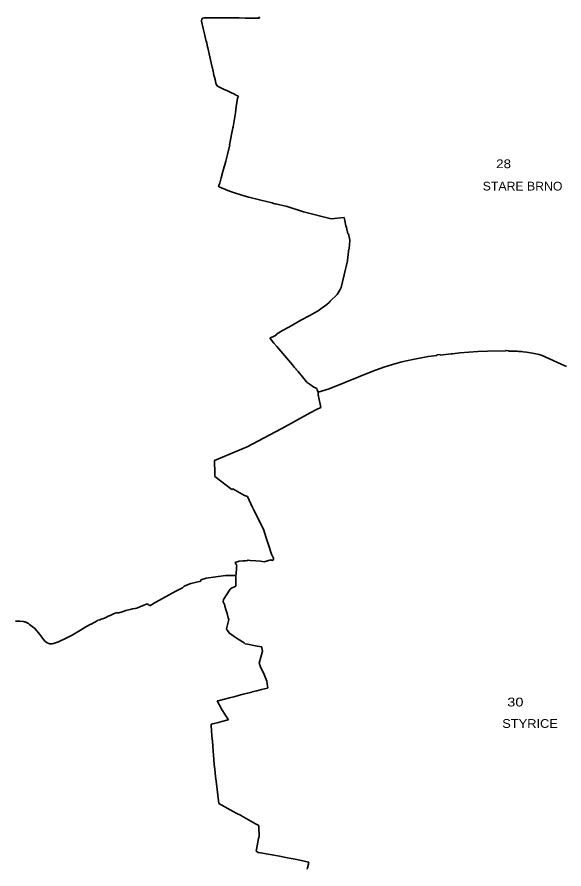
# Model space of a CAD drawing. Extents: x -610940 to -588976, y -1170376 to -1149800.
# Drawn here: x -600639 to -599073, y -1163066 to -1160628 of the extents above; entities that cross this region are included whole.
import ezdxf

# ---------------------------------------------------------------- set-up
doc = ezdxf.new("R2010")
doc.units = 0
doc.header["$LTSCALE"] = 10
doc.layers.add('54', color=7, linetype='Continuous', lineweight=35)
doc.layers.add('55', color=7, linetype='Continuous')
doc.layers.add('56', color=7, linetype='Continuous')

msp = doc.modelspace()

# ---------------------------------------------------------------- linework, layer by layer
at = {"layer": '54'}
for p, q in [((-600103.3, -1160629.78), (-600107.3, -1160631.31)), ((-600103.3, -1160629.78), (-600088.08, -1160629.91)), ((-600085.37, -1160629.93), (-600072.54, -1160630)), ((-600002.59, -1160630.29), (-599986.11, -1160630.73)), ((-599986.11, -1160630.73), (-599979.88, -1160630.93)), ((-599945.32, -1160628.56), (-599945.69, -1160627.27)), ((-599944.67, -1160630.86), (-599945.32, -1160628.56)), ((-600109.32, -1160633.17), (-600110.87, -1160639.41)), ((-600105.68, -1160660.84), (-600110.87, -1160639.41)), ((-600109.32, -1160633.17), (-600107.3, -1160631.31)), ((-599979.88, -1160630.93), (-599979.11, -1160630.96)), ((-599979.11, -1160630.96), (-599965.69, -1160630.92)), ((-600098, -1160693.72), (-600102.01, -1160676.44)), ((-600097.36, -1160696.48), (-600098, -1160693.72)), ((-600095.82, -1160703.17), (-600097.36, -1160696.48)), ((-600093.54, -1160712.95), (-600095.82, -1160703.17)), ((-600092.87, -1160715.78), (-600093.54, -1160712.95)), ((-600080.89, -1160768.02), (-600092.87, -1160715.78)), ((-600080.17, -1160771.14), (-600080.89, -1160768.02)), ((-600079.48, -1160774.16), (-600080.17, -1160771.14)), ((-600077.36, -1160783.38), (-600079.48, -1160774.16)), ((-600076.45, -1160787.46), (-600077.36, -1160783.38)), ((-600076.01, -1160789.45), (-600076.45, -1160787.46)), ((-600069.52, -1160816.92), (-600071.93, -1160807.07)), ((-600069.52, -1160816.92), (-600068.55, -1160820.02)), ((-600066.77, -1160823.08), (-600068.55, -1160820.02)), ((-600066.77, -1160823.08), (-600064.5, -1160825.65)), ((-600061.27, -1160827.81), (-600064.5, -1160825.65)), ((-600058.82, -1160828.98), (-600061.27, -1160827.81)), ((-600036.69, -1160839.42), (-600047.79, -1160834.31)), ((-600015.91, -1160849.13), (-600026.48, -1160844.23)), ((-600017.13, -1160924.54), (-600013.14, -1160901.76)), ((-600020.88, -1160944.64), (-600020.28, -1160942.07)), ((-600020.28, -1160942.07), (-600017.13, -1160924.54)), ((-599699.51, -1161214.79), (-599702.32, -1161201.68)), ((-599685.63, -1161266.21), (-599690, -1161248.08)), ((-599687.71, -1161286.68), (-599687.35, -1161282.76)), ((-599686.26, -1161271.3), (-599685.63, -1161266.21)), ((-599689.73, -1161299.35), (-599689.5, -1161297.25)), ((-599722.11, -1161421.7), (-599714.05, -1161407.67)), ((-599714.05, -1161407.67), (-599710.88, -1161402.16)), ((-599901.13, -1161540.23), (-599914.85, -1161547.36)), ((-599910.52, -1161552.57), (-599914.85, -1161547.36)), ((-599910.52, -1161552.57), (-599903.3, -1161561.19)), ((-599901.13, -1161540.23), (-599895.55, -1161537.33)), ((-599896.4, -1161536.03), (-599895.55, -1161537.33)), ((-599895.23, -1161570.77), (-599903.3, -1161561.19)), ((-599850.32, -1161623.75), (-599895.23, -1161570.77)), ((-599505.29, -1161607.84), (-599461.75, -1161599.91)), ((-599461.75, -1161599.91), (-599436.5, -1161596.37)), ((-599436.65, -1161595.16), (-599427.23, -1161593.95)), ((-599436.5, -1161596.37), (-599436.65, -1161595.16)), ((-599427.23, -1161593.95), (-599426.97, -1161595.51)), ((-599426.97, -1161595.51), (-599396.23, -1161591.99)), ((-599396.23, -1161591.99), (-599392.18, -1161591.53)), ((-599392.18, -1161591.53), (-599370.97, -1161589.44)), ((-599370.97, -1161589.44), (-599319.39, -1161585.61)), ((-599319.39, -1161585.61), (-599292.08, -1161584.67)), ((-599292.08, -1161584.67), (-599240.09, -1161583.7)), ((-599240.09, -1161583.7), (-599240.14, -1161582.76)), ((-599238.59, -1161582.77), (-599232.38, -1161582.84)), ((-599230.74, -1161582.85), (-599230.74, -1161583.8)), ((-599230.74, -1161583.8), (-599218.48, -1161583.93)), ((-599218.48, -1161583.93), (-599218.01, -1161583.89)), ((-599218.01, -1161583.89), (-599214.85, -1161584.1)), ((-599200.08, -1161585.08), (-599203.24, -1161584.87)), ((-599200.08, -1161585.08), (-599199.58, -1161585.1)), ((-599189.94, -1161585.84), (-599179.82, -1161586.62)), ((-599179.82, -1161586.62), (-599163, -1161589.64)), ((-599163, -1161589.64), (-599143.65, -1161594.17)), ((-599143.65, -1161594.17), (-599135.02, -1161596.97)), ((-599135.02, -1161596.97), (-599114.73, -1161605.82)), ((-599114.73, -1161605.82), (-599080.75, -1161621.2)), ((-599850.32, -1161623.75), (-599844.18, -1161630.77)), ((-599606.5, -1161636.65), (-599589.06, -1161630.32)), ((-599589.06, -1161630.32), (-599564, -1161622)), ((-599564, -1161622), (-599537.18, -1161614.79)), ((-599537.18, -1161614.79), (-599505.29, -1161607.84)), ((-599080.75, -1161621.2), (-599065.94, -1161628.12)), ((-599840.06, -1161635.49), (-599844.18, -1161630.77)), ((-599838.52, -1161637.29), (-599840.06, -1161635.49)), ((-599838.52, -1161637.29), (-599837.63, -1161638.37)), ((-599834.1, -1161642.64), (-599837.63, -1161638.37)), ((-599834.1, -1161642.64), (-599821.62, -1161657.7)), ((-599745.4, -1161692.26), (-599615.27, -1161639.75)), ((-599615.27, -1161639.75), (-599606.5, -1161636.65)), ((-599807.8, -1161673.56), (-599799.85, -1161680.09)), ((-599788.86, -1161687.22), (-599799.85, -1161680.09)), ((-599776.36, -1161701.3), (-599757.25, -1161696.22)), ((-599757.25, -1161696.22), (-599745.4, -1161692.26)), ((-599979.51, -1161857.91), (-599882.14, -1161806.57)), ((-600024.12, -1161979.68), (-600072.54, -1161943.35)), ((-600021.31, -1161978.3), (-600024.12, -1161979.68)), ((-599961.47, -1162037.67), (-599962.52, -1162035.22)), ((-599932.79, -1162093.6), (-599961.47, -1162037.67)), ((-599925.25, -1162118.38), (-599932.79, -1162093.6)), ((-599918.57, -1162138.88), (-599925.25, -1162118.38)), ((-599910.5, -1162164.95), (-599918.57, -1162138.88)), ((-599904.71, -1162176.49), (-599910.5, -1162164.95)), ((-599903.75, -1162177.62), (-599904.71, -1162176.49)), ((-600112.4, -1162239.03), (-600097.62, -1162233.99)), ((-600112.4, -1162239.03), (-600112.16, -1162242.62)), ((-600097.62, -1162233.99), (-600042.31, -1162226.63)), ((-600033.31, -1162226.17), (-600012.18, -1162226.15)), ((-600012.46, -1162244.45), (-600012.18, -1162226.15)), ((-600183.82, -1162271.06), (-600164.74, -1162261.15)), ((-600164.74, -1162261.15), (-600160.13, -1162257.05)), ((-600160.13, -1162257.05), (-600158.3, -1162256.28)), ((-600158.3, -1162256.28), (-600141.05, -1162249.04)), ((-600141.05, -1162249.04), (-600112.16, -1162242.62)), ((-600012.76, -1162256.79), (-600012.46, -1162244.45)), ((-600222.07, -1162292.39), (-600202.95, -1162281.63)), ((-600202.95, -1162281.63), (-600183.82, -1162271.06)), ((-600271.06, -1162309.32), (-600265.95, -1162307.55)), ((-600265.95, -1162307.55), (-600264.38, -1162308.65)), ((-600264.38, -1162308.65), (-600260.3, -1162311.49)), ((-600260.3, -1162311.49), (-600258.2, -1162312.95)), ((-600258.2, -1162312.95), (-600240.96, -1162303.07)), ((-600240.96, -1162303.07), (-600222.07, -1162292.39)), ((-600366.85, -1162338.13), (-600364.05, -1162336.83)), ((-600364.05, -1162336.83), (-600352.79, -1162332.42)), ((-600352.79, -1162332.42), (-600350.1, -1162334.51)), ((-600350.1, -1162334.51), (-600335.03, -1162328.94)), ((-600335.03, -1162328.94), (-600327.33, -1162326.6)), ((-600327.33, -1162326.6), (-600314.8, -1162323.43)), ((-600314.8, -1162323.43), (-600308.43, -1162321.7)), ((-600308.43, -1162321.7), (-600301.74, -1162320.9)), ((-600643.07, -1162357.45), (-600634.44, -1162356.94)), ((-600634.44, -1162356.94), (-600630.84, -1162356.73)), ((-600630.84, -1162356.73), (-600620.22, -1162358.38)), ((-600615.57, -1162359.11), (-600611.4, -1162360.5)), ((-600611.4, -1162360.5), (-600606.21, -1162363.37)), ((-600426.32, -1162365.36), (-600409.64, -1162356.23)), ((-600401.4, -1162352.95), (-600398.02, -1162351.71)), ((-600398.02, -1162351.71), (-600388.65, -1162348.25)), ((-600388.65, -1162348.25), (-600383.01, -1162345.61)), ((-600383.01, -1162345.61), (-600375.62, -1162342.2)), ((-600375.62, -1162342.2), (-600374.19, -1162341.56)), ((-600374.19, -1162341.56), (-600372.43, -1162340.72)), ((-600606.21, -1162363.37), (-600602.72, -1162366.32)), ((-600602.72, -1162366.32), (-600595.6, -1162371.79)), ((-600595.6, -1162371.79), (-600588.93, -1162377.45)), ((-600588.93, -1162377.45), (-600582.79, -1162383.92)), ((-600582.79, -1162383.92), (-600576.52, -1162391.45)), ((-600478.14, -1162395.63), (-600462.25, -1162385.44)), ((-600462.25, -1162385.44), (-600445.03, -1162374.73)), ((-600445.03, -1162374.73), (-600443.97, -1162373.94)), ((-600443.97, -1162373.94), (-600427.04, -1162365.7)), ((-600427.04, -1162365.7), (-600426.32, -1162365.36)), ((-600576.52, -1162391.45), (-600567.65, -1162402.59)), ((-600567.65, -1162402.59), (-600559.89, -1162413.15)), ((-600520.42, -1162415.85), (-600496.63, -1162404.65)), ((-600496.63, -1162404.65), (-600478.96, -1162396.23)), ((-600478.96, -1162396.23), (-600478.14, -1162395.63)), ((-600559.89, -1162413.15), (-600552.51, -1162419.01)), ((-600552.51, -1162419.01), (-600548.16, -1162421.13)), ((-600548.16, -1162421.13), (-600544.9, -1162422.25)), ((-600544.9, -1162422.25), (-600541.3, -1162422.28)), ((-600541.3, -1162422.28), (-600537.77, -1162421.55)), ((-600537.77, -1162421.55), (-600534.47, -1162420.85)), ((-600534.47, -1162420.85), (-600520.42, -1162415.85)), ((-600074.18, -1162767.5), (-600076.28, -1162739.84)), ((-600068.44, -1162814.92), (-600070.2, -1162801.12)), ((-600060.61, -1162879.01), (-600068.44, -1162814.92)), ((-599999.32, -1162912.65), (-599996.36, -1162914.29)), ((-599955.95, -1162936.72), (-599996.36, -1162914.29)), ((-599950.48, -1162939.76), (-599955.95, -1162936.72)), ((-599946.3, -1162942.08), (-599950.48, -1162939.76)), ((-599946.2, -1162947.52), (-599946.3, -1162942.08)), ((-599945.76, -1162971.13), (-599946.2, -1162947.52)), ((-599953.12, -1163010.59), (-599947.21, -1162979.44)), ((-599954.03, -1163015), (-599953.12, -1163010.59)), ((-599859.21, -1163035.07), (-599892.05, -1163028.76))]:
    msp.add_line(p, q, dxfattribs=at)
for points in [[(-600088.08, -1160629.91), (-600087.71, -1160629.91), (-600086.69, -1160629.92), (-600086.33, -1160629.98), (-600085.37, -1160629.93)], [(-600072.54, -1160630), (-600068.88, -1160630.09), (-600046.08, -1160630.17)], [(-600046.08, -1160630.17), (-600041.68, -1160630.17), (-600033.36, -1160630.13), (-600030.62, -1160630.26), (-600026.5, -1160630.27), (-600024.2, -1160630.22), (-600021.96, -1160630.24)], [(-600021.96, -1160630.24), (-600019.23, -1160630.33), (-600012.52, -1160630.25), (-600010.87, -1160630.31), (-600002.59, -1160630.29)], [(-599965.69, -1160630.92), (-599955.45, -1160630.89), (-599945.71, -1160630.86), (-599944.67, -1160630.86)], [(-600102.01, -1160676.44), (-600104.02, -1160668.14), (-600105.68, -1160660.84)], [(-600071.93, -1160807.07), (-600073.69, -1160799.85), (-600074.98, -1160794.08), (-600076.01, -1160789.45)], [(-600047.79, -1160834.31), (-600057.37, -1160829.73), (-600057.69, -1160829.51), (-600058.36, -1160829.14), (-600058.82, -1160828.98)], [(-600026.48, -1160844.23), (-600034.51, -1160840.47), (-600036.69, -1160839.42)], [(-600004.83, -1160854.5), (-600013.92, -1160850.14), (-600014.26, -1160849.96), (-600015.3, -1160849.44), (-600015.62, -1160849.28), (-600015.91, -1160849.13)], [(-600013.14, -1160901.76), (-600011.01, -1160885.38), (-600007.56, -1160859.9), (-600005.86, -1160856.55), (-600004.83, -1160854.5)], [(-600029.47, -1160993.42), (-600030.04, -1160993.24), (-600020.88, -1160944.64)], [(-599898.7, -1161162.24), (-599900.76, -1161162.29), (-599904.58, -1161161.31), (-599906.46, -1161160.46), (-599908.68, -1161159.77), (-599941.16, -1161151.69), (-599975.05, -1161143.25), (-599992.6, -1161138.37), (-600022.21, -1161129.09), (-600027.25, -1161127.68), (-600035.23, -1161124.14), (-600060.19, -1161113.93), (-600061.42, -1161112.61), (-600061.66, -1161110.46), (-600061.36, -1161110.25), (-600059.52, -1161105.66), (-600058.54, -1161103.09), (-600054.07, -1161088.16), (-600049.18, -1161070.38), (-600041.23, -1161040.31), (-600036.41, -1161021.43), (-600029.47, -1160993.42)], [(-599702.32, -1161201.68), (-599739.03, -1161205.3), (-599818.82, -1161185.87), (-599865.5, -1161170.1), (-599898.7, -1161162.24)], [(-599699.51, -1161214.79), (-599699.35, -1161215.5), (-599698.21, -1161220.69)], [(-599695.83, -1161230.53), (-599697.15, -1161225.76), (-599698.21, -1161220.69)], [(-599690, -1161248.08), (-599691.59, -1161248.5), (-599695.83, -1161230.53)], [(-599689.22, -1161294.6), (-599688.33, -1161289.4), (-599687.85, -1161287.45), (-599687.71, -1161286.68)], [(-599687.35, -1161282.76), (-599687.05, -1161279.34), (-599686.64, -1161274.96), (-599686.26, -1161271.3)], [(-599689.73, -1161299.35), (-599690.62, -1161307.5), (-599692.37, -1161323.54), (-599692.93, -1161325.91), (-599695.87, -1161338.34)], [(-599689.5, -1161297.25), (-599689.36, -1161295.65), (-599689.22, -1161294.6)], [(-599710.88, -1161402.16), (-599698.49, -1161349.38), (-599695.87, -1161338.34)], [(-599896.4, -1161536.03), (-599878.6, -1161525.25), (-599861, -1161515.13), (-599825.96, -1161495.89), (-599800.88, -1161482.07), (-599787.3, -1161474.58), (-599777.1, -1161468.42), (-599764.98, -1161460.44), (-599751.94, -1161450.4), (-599745.5, -1161445.06), (-599741.96, -1161441.27), (-599722.11, -1161421.7)], [(-599240.14, -1161582.76), (-599239.71, -1161582.74), (-599239.04, -1161582.76), (-599238.59, -1161582.77)], [(-599232.38, -1161582.84), (-599231.88, -1161582.84), (-599231.05, -1161582.85), (-599230.74, -1161582.85)], [(-599214.85, -1161584.1), (-599210.46, -1161584.39), (-599207.31, -1161584.6), (-599203.24, -1161584.87)], [(-599199.58, -1161585.1), (-599194.59, -1161585.48), (-599189.94, -1161585.84)], [(-599807.8, -1161673.56), (-599809.58, -1161671.67), (-599821.62, -1161657.7)], [(-599776.36, -1161701.3), (-599779.22, -1161694.76), (-599780.74, -1161691.25), (-599784.6, -1161689.38), (-599788.86, -1161687.22)], [(-599769.24, -1161745.31), (-599771.09, -1161735.94), (-599776.19, -1161709.38), (-599776.57, -1161707.29), (-599776.99, -1161704.72), (-599777.05, -1161704.03), (-599776.23, -1161703.87), (-599776.36, -1161701.3)], [(-599799.97, -1161760.89), (-599781.75, -1161750.78), (-599769.24, -1161745.31)], [(-599882.14, -1161806.57), (-599880.61, -1161805.7), (-599799.97, -1161760.89)], [(-600072.75, -1161934.56), (-600072.99, -1161896.91), (-599979.51, -1161857.91)], [(-600072.54, -1161943.35), (-600072.7, -1161941.28), (-600072.75, -1161934.56)], [(-599962.52, -1162035.22), (-599964.07, -1162031.89), (-599965.19, -1162029.55), (-599978.23, -1162002.2), (-599978.99, -1162000.4), (-599987.32, -1161997.1), (-600014.67, -1161982.44), (-600021.31, -1161978.3)], [(-600009.46, -1162198.97), (-600013.94, -1162188.76), (-600003.26, -1162185.17), (-599992.01, -1162184.53), (-599983.49, -1162184.14)], [(-599983.49, -1162184.14), (-599978.91, -1162183.65), (-599976.74, -1162182.66), (-599971.52, -1162183.03), (-599954.86, -1162184.11), (-599941.86, -1162185.36), (-599930.85, -1162187.23)], [(-599930.85, -1162187.23), (-599912.5, -1162181.36), (-599909.81, -1162182.17), (-599908.31, -1162182.48), (-599906.59, -1162183.01), (-599903.75, -1162177.62)], [(-600012.18, -1162226.15), (-600011.71, -1162221.11), (-600011.61, -1162220.24), (-600011.22, -1162215.93), (-600010.76, -1162210.79)], [(-600010.76, -1162210.79), (-600009.98, -1162202.47), (-600009.46, -1162198.97)], [(-600042.31, -1162226.63), (-600039.65, -1162226.24), (-600033.31, -1162226.17)], [(-600028.95, -1162265.29), (-600024.68, -1162262.95), (-600012.76, -1162256.79)], [(-600044.19, -1162314.11), (-600044.12, -1162311.33), (-600048.44, -1162301.26), (-600048.07, -1162294.95), (-600028.95, -1162265.29)], [(-600279.66, -1162312.7), (-600285.42, -1162315.34), (-600296.08, -1162320.23)], [(-600279.66, -1162312.7), (-600275.99, -1162311.02), (-600271.06, -1162309.32)], [(-600301.74, -1162320.9), (-600299.85, -1162320.68), (-600296.08, -1162320.23)], [(-600034.24, -1162347.1), (-600037.58, -1162335.07), (-600040.86, -1162323.14), (-600044.19, -1162314.11)], [(-600620.22, -1162358.38), (-600618.94, -1162358.58), (-600615.57, -1162359.11)], [(-600409.64, -1162356.23), (-600406.97, -1162353.68), (-600401.4, -1162352.95)], [(-600372.43, -1162340.72), (-600370.3, -1162339.73), (-600366.85, -1162338.13)], [(-600005.32, -1162408.72), (-600014.53, -1162402.95), (-600017.57, -1162400.63), (-600030.68, -1162391.68), (-600037.35, -1162382.35), (-600039.49, -1162379.4), (-600034.41, -1162359.5), (-600032.75, -1162352.47), (-600034.24, -1162347.1)], [(-599955.88, -1162427.24), (-599979.02, -1162422.89), (-599985.28, -1162421.8), (-599988.98, -1162419.35), (-600005.32, -1162408.72)], [(-599920.48, -1162548.2), (-599922.27, -1162536.47), (-599923.36, -1162528.7), (-599931.53, -1162509.87), (-599941.4, -1162487.24), (-599942.64, -1162484.51), (-599945.72, -1162477.46), (-599940.87, -1162459.57), (-599936.33, -1162442.68), (-599937.69, -1162433.45), (-599938.16, -1162430.64), (-599938.97, -1162430.45), (-599955.88, -1162427.24)], [(-600065.69, -1162585.09), (-600059.19, -1162583.61), (-600045, -1162580), (-600030.86, -1162576.42), (-600017.68, -1162573.12), (-600004.54, -1162569.48), (-599990.91, -1162566.07), (-599978.15, -1162562.71), (-599966.87, -1162559.8), (-599965.73, -1162559.69), (-599952.07, -1162556.25), (-599938.58, -1162552.85), (-599922.13, -1162548.63), (-599920.48, -1162548.2)], [(-600050.77, -1162612.62), (-600051.1, -1162612.01), (-600053.91, -1162606.83), (-600055.21, -1162604.48), (-600063.46, -1162589.21), (-600065.69, -1162585.09)], [(-600033.8, -1162639.28), (-600041.02, -1162628.08), (-600046.18, -1162619.96), (-600050.77, -1162612.62)], [(-600083.23, -1162652.19), (-600079, -1162651.1), (-600066.01, -1162647.71), (-600052.27, -1162644.12), (-600038.06, -1162640.39), (-600033.8, -1162639.28)], [(-600079.32, -1162701.54), (-600080.6, -1162685.38), (-600081.83, -1162669.8), (-600082.9, -1162656.38), (-600083.23, -1162652.19)], [(-600076.28, -1162739.84), (-600077.09, -1162729.68), (-600078.34, -1162713.93), (-600079.32, -1162701.54)], [(-600070.2, -1162801.12), (-600072.58, -1162781.03), (-600074.18, -1162767.5)], [(-599999.32, -1162912.65), (-600009.07, -1162907.3), (-600019.94, -1162901.35), (-600060.61, -1162879.01)], [(-599947.21, -1162979.44), (-599946.59, -1162975.89), (-599945.76, -1162971.13)], [(-599946.75, -1163019.31), (-599948.18, -1163018.8), (-599954.03, -1163015)], [(-599892.05, -1163028.76), (-599942.07, -1163019.97), (-599946.75, -1163019.31)], [(-599803.35, -1163046.3), (-599842.84, -1163038.18), (-599859.21, -1163035.07)], [(-599808.28, -1163067.14), (-599807.2, -1163062.59), (-599804.73, -1163052.14)], [(-599804.73, -1163052.14), (-599804.22, -1163050), (-599804.15, -1163049.71), (-599803.35, -1163046.3)]]:
    msp.add_lwpolyline(points, dxfattribs=at)

# ---------------------------------------------------------------- texts
at = {"layer": '55'}
for s, width, p in [('STARE BRNO', 1.05, (-599305.55, -1161124.4)), ('STYRICE ', 1.1, (-599249.73, -1162662.4))]:
    msp.add_text(s, height=25, dxfattribs=dict(at, width=width)).set_placement(p)
at = {"layer": '56'}
for s, width, p in [('28 ', 1.15, (-599267.23, -1161060.42)), ('30 ', 1.25, (-599235.38, -1162601.03))]:
    msp.add_text(s, height=25, dxfattribs=dict(at, width=width)).set_placement(p)

doc.saveas('drawing.dxf')
